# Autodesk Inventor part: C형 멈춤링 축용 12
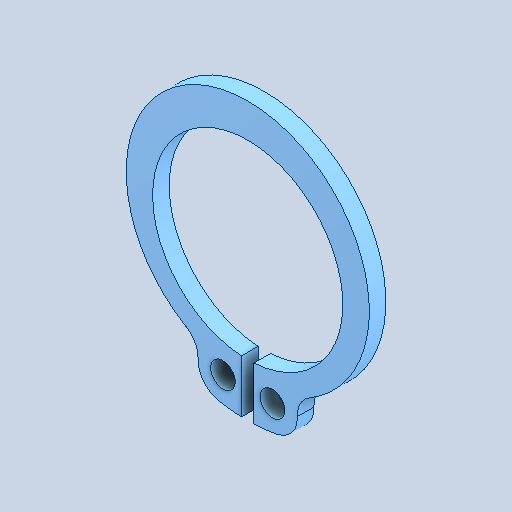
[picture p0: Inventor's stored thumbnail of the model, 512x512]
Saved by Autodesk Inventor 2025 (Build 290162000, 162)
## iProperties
Created: 2026-07
Part Number: C형 멈춤링 축용 12
Material: 강철, 연강
Description: 리테이닝 링(C형)
Document SubType Name: Modeling
Designer: KDI
Density: 7.85 g/cm^3
Appearance: 기본값
Author: jhkim
Sending System: Autodesk Inventor 2027
Preprocessor: ST-DEVELOPER v20.1
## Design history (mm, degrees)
feature "Solid1"
node "솔리드1"
